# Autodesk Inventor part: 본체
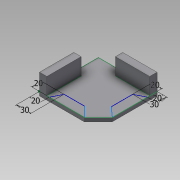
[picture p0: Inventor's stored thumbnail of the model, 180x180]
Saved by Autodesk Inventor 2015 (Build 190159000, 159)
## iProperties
Created: 2019-04
Part Number: 본체
Material: 일반
Document SubType Name: Modeling
Designer: SCD-A02
Density: 1 g/cm^3
Appearance: 기본값
Author: SCD-A02
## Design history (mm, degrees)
sketch "스케치2"
  geometry: L1 (0, 0)-(120, 0); L2 (120, 0)-(120, 120); L3 (120, 120)-(0, 120); L4 (0, 120)-(0, 0)
  constraints: 8 end point, 2 parallel, 1 horizontal, 1 perpendicular
  dimensions: "d2" = 120 distance of L2.end L3.end; "d3" = 120 distance of L1.end L2.end
extrude "돌출1" new body sketch "스케치2" distance "d4" = 8; taper "d5" = 0 deg
sketch "스케치3"
  geometry: L1 (0, 0)-(120, 0) reference; L2 (0, 0)-(120, 0) reference; L3 (120, 0)-(120, 120) reference; L4 (120, 120)-(0, 120) reference; L5 (0, 120)-(0, 0) reference; L6 (120, 28.284)-(91.716, 0); L7 (120, 28.284)-(120, 0); L8 (91.716, 0)-(120, 0)
  constraints: 6 end point, 2 point on line, 1 collinear, 1 perpendicular
  dimensions: "d8" = 45 deg angle of L6 L1; "d9" = 40 distance of L6.start L6.end
extrude "돌출2" cut sketch "스케치3" distance "d10" = 8; taper "d11" = 0 deg
sketch "스케치4"
  geometry: L1 (120, 28.284)-(120, 120) reference; L2 (120, 120)-(0, 120) reference; L3 (0, 120)-(0, 0) reference; L4 (0, 0)-(91.716, 0) reference; L5 (0, 70)-(15, 70); L6 (15, 70)-(15, 0); L7 (0, 0)-(0, 70); L8 (0, 0)-(15, 0); L9 (50, 120)-(50, 105); L10 (50, 105)-(120, 105); L11 (120, 120)-(50, 120); L12 (120, 120)-(120, 105)
  constraints: 16 end point, 4 collinear, 4 point on line, 3 perpendicular, 1 horizontal
  dimensions: "d12" = 50 distance from line of L2.end L5; "d13" = 15 distance of L5.start L5.end; "d14" = 15 distance of L9.start L9.end; "d15" = 50 distance from line of L2.end L9
extrude "돌출3" join sketch "스케치4" distance "d16" = 34; taper "d17" = 0 deg
sketch "스케치6"
  geometry: L1 (50, 105)-(50, 120) reference; L2 (50, 120)-(0, 120) reference; L3 (0, 120)-(0, 70) reference; L4 (0, 70)-(15, 70) reference; L5 (15, 70)-(15, 0) reference; L6 (15, 0)-(91.716, 0) reference; L7 (91.716, 0)-(120, 28.284) reference; L8 (120, 28.284)-(120, 105) reference; L9 (120, 105)-(50, 105) reference; L10 (20, 0)-(30, 20); L11 (30, 20)-(71.729, 20); L12 (71.729, 20)-(91.716, 0); L13 (120, 28.284)-(100, 46.529); L14 (100, 46.529)-(100, 90); L15 (100, 90)-(120, 100); L16 (120, 120)-(0, 120) reference; L17 (120, 28.284)-(120, 120) reference; 1 further point
  constraints: 12 end point, 2 point on line, 1 horizontal, 1 vertical
  dimensions: "d19" = 20 distance of point (0, 0) L10.start; "d20" = 20 distance from line of L16 L15.end; "d21" = 30 horizontal distance of point (0, 0) L10.end; "d22" = 30 distance from line of L16 L14.end; "d23" = 20 distance between parallel lines of L6 L11; "d24" = 20 distance between parallel lines of L17 L14
node "솔리드1"
node "투영된 루프1"
